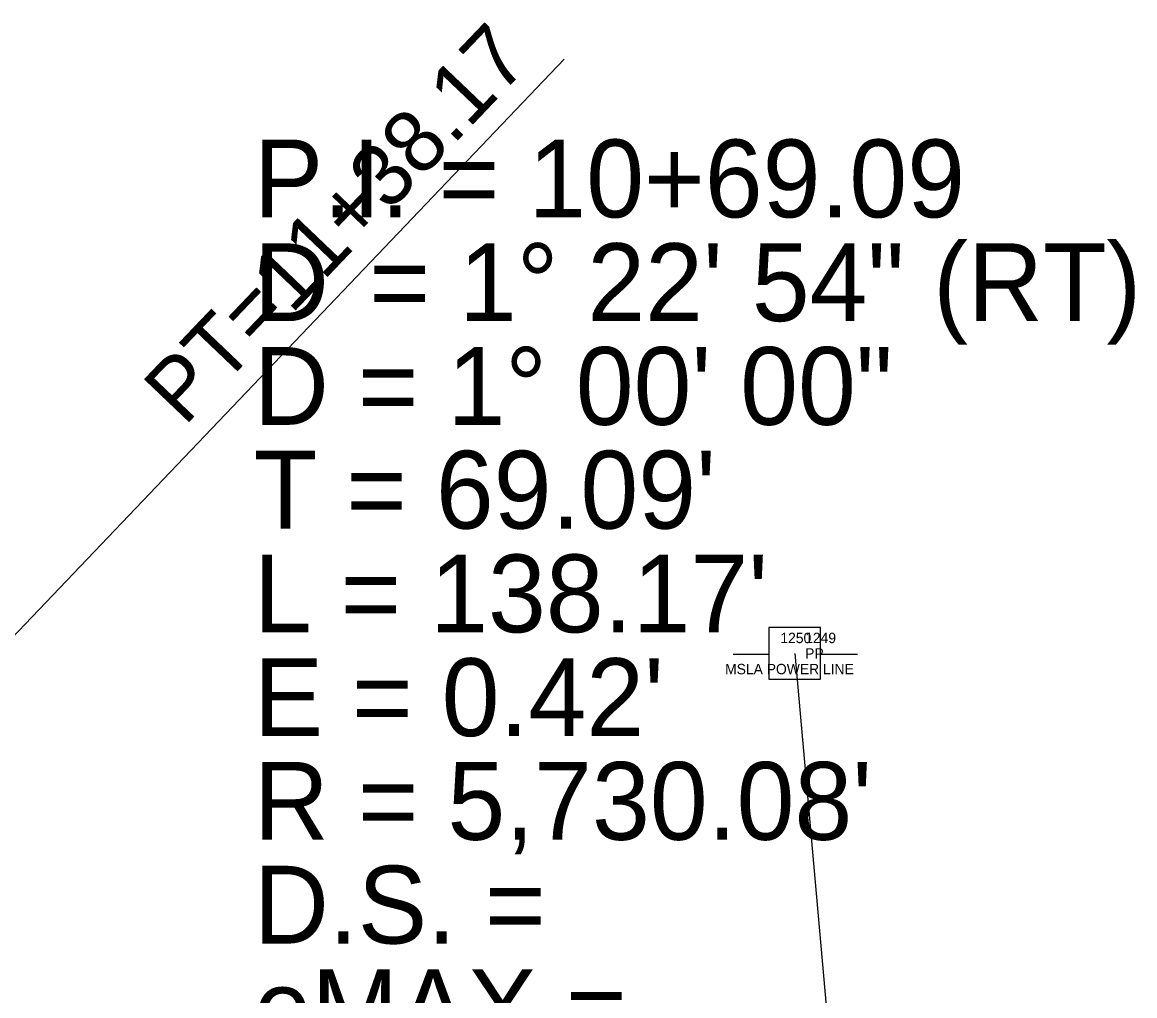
# Model space of a CAD drawing. Extents: x 1812340 to 1815011, y 1177659 to 1180159.
# Drawn here: x 1813993.7 to 1814100.9, y 1178509 to 1178602.8 of the extents above; entities that cross this region are included whole.
import ezdxf

# ---------------------------------------------------------------- set-up
doc = ezdxf.new("R2010")
doc.units = 0
for name, color, linetype in [('RD_EX_Misc', 7, 'Continuous'), ('RD_EX_Misc_txCode', 7, 'Continuous'), ('RD_EX_UT', 7, 'Continuous'), ('RD_EX_UT_txCode', 7, 'Continuous'), ('RD_HC_CL', 7, 'Continuous'), ('RD_HC_Data', 7, 'Continuous'), ('RD_SMD_Locator', 7, 'Continuous')]:
    doc.layers.add(name, color=color, linetype=linetype)

msp = doc.modelspace()

# ---------------------------------------------------------------- linework, layer by layer
at = {"layer": 'RD_EX_Misc'}
msp.add_line((1814068.17, 1178541.96), (1814086.12, 1178341.27), dxfattribs=at)
at = {"layer": 'RD_EX_UT'}
for p, q in [((1814070.66, 1178544.47), (1814065.66, 1178544.47)), ((1814065.66, 1178544.47), (1814065.66, 1178539.47)), ((1814070.66, 1178539.47), (1814070.66, 1178544.47)), ((1814062.23, 1178541.91), (1814065.7, 1178541.91)), ((1814070.59, 1178541.91), (1814074.23, 1178541.91)), ((1814065.66, 1178539.47), (1814070.66, 1178539.47))]:
    msp.add_line(p, q, dxfattribs=at)
at = {"layer": 'RD_HC_CL'}
msp.add_arc((1817921.84, 1182660.75), 5730.08, 226.33932, 227.720866, dxfattribs=at)
at = {"layer": 'RD_HC_Data'}
msp.add_line((1813965.88, 1178515.37), (1814045.93, 1178599.26), dxfattribs=at)
at = {"layer": 'RD_SMD_Locator'}
msp.add_circle((1814068.17, 1178541.96), 0.001, dxfattribs=at)

# ---------------------------------------------------------------- texts
at = {"layer": 'RD_EX_Misc_txCode'}
for s, p in [('1250', (1814066.78, 1178542.96)), ('MSLA POWER LINE', (1814061.45, 1178539.96))]:
    msp.add_text(s, height=1, dxfattribs=at).set_placement(p)
at = {"layer": 'RD_EX_UT_txCode'}
for s, p in [('1249', (1814069.17, 1178542.96)), ('PP', (1814069.17, 1178541.46))]:
    msp.add_text(s, height=1, dxfattribs=at).set_placement(p)
at = {"layer": 'RD_HC_Data'}
msp.add_text('PT=11+38.17', height=6, rotation=46.3393, dxfattribs=at).set_placement((1814009.3, 1178563.78))
for s, p in [('P.I. = 10+69.09', (1814016, 1178584)), ('    = 1%%d 22\' 54" (RT)', (1814016, 1178574)), ('D', (1814016, 1178574)), ('D = 1%%d 00\' 00"', (1814016, 1178564)), ("T = 69.09'", (1814016, 1178554)), ("L = 138.17'", (1814016, 1178544)), ("E = 0.42'", (1814016, 1178534)), ("R = 5,730.08'", (1814016, 1178524)), ('D.S. = ', (1814016, 1178514)), ('eMAX = ', (1814016, 1178504))]:
    msp.add_text(s, height=7.5, dxfattribs=at).set_placement(p)

doc.saveas('drawing.dxf')
